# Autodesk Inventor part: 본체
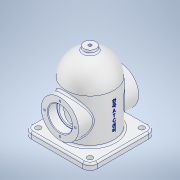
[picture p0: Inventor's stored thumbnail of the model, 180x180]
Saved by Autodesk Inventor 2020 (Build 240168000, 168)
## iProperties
Created: 2021-07
Part Number: 본체
Material: 알루미늄 6061
Document SubType Name: Modeling
Designer: Owner
Density: 2.7 g/cm^3
Appearance: 알루미늄 - 평지
Mass: 865.906 g
Surface Area: 800.746 cm^2
Volume: 320.706 cm^3
Author: Owner
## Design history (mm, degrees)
sketch "스케치1"
  geometry: C1 r 40 at (0, 0); 1 further point
  constraints: 1 centre point, 1 coincident
  dimensions: "d0" = 80 diameter of C1
extrude "돌출1" new body sketch "스케치1" distance "d1" = 124; taper "d2" = 0 deg
fillet "모깎기1" dims "d3" = 40
feature "쉘1" dims "d4" = 8
node "작업 평면1"
sketch "스케치2"
  geometry: C1 r 31 at (0, 48); 1 further point
  constraints: 1 centre point, 1 vertical alignment
  dimensions: "d6" = 62 diameter of C1; "d7" = 48 distance of point (0, 0) C1.centre
extrude "돌출2" join sketch "스케치2" stored distance "d8" = 124; taper "d9" = 0 deg
sketch "스케치3"
  geometry: C1 r 31 at (0, 0) reference; 2 further points
  constraints: 1 coincident
hole "구멍1" sketch "스케치3" at (0, 0) diameter "d10" = 33; stored, may be unused: countersink angle "d14" = 90 deg, drill point angle "d16" = 118 deg; dims "d11" = 6, "d12" = 40, "d13" = 15, "d15" = 49.25
sketch "스케치4"
  geometry: C1 r 16.5 at (0, 0) reference; 2 further points
  constraints: 1 vertical alignment
  dimensions: "d17" = 25.5 distance of C1.centre point (0, 25.5)
hole "구멍2" sketch "스케치4" at (0, 25.5) diameter "d18" = 3.242; stored, may be unused: countersink angle "d22" = 90 deg, drill point angle "d24" = 118 deg; dims "d19" = 8, "d20" = 40, "d21" = 15, "d23" = 10
sketch "스케치5"
  geometry: L1 (-55, 55)-(55, 55); L2 (55, 55)-(55, -55); L3 (55, -55)-(-55, -55); L4 (-55, -55)-(-55, 55); L5 (-55, 55)-(55, -55); L6 (55, 55)-(-55, -55); C1 r 40 at (0, 0) reference; 1 further point
  constraints: 12 end point, 2 midpoint, 2 parallel, 1 horizontal, 1 perpendicular
  dimensions: "d28" = 110 distance of L2.end L3.end; "d29" = 110 distance of L1.end L2.end
extrude "돌출3" join sketch "스케치5" distance "d30" = 10; taper "d31" = 0 deg
fillet "모깎기2" dims "d32" = 12
fillet "모깎기3" dims "d33" = 3
fillet "모깎기4" dims "d34" = 3
node "작업 평면2"
sketch "스케치6"
  geometry: C1 r 10 at (0, 0); 1 further point
  constraints: 1 centre point, 1 coincident
  dimensions: "d36" = 20 diameter of C1
extrude "돌출4" join sketch "스케치6" stored distance "d37" = 10; taper "d38" = 0 deg
sketch "스케치7"
  geometry: C1 r 10 at (0, 0) reference; 2 further points
  constraints: 1 coincident
hole "구멍3" sketch "스케치7" at (0, 0) diameter "d39" = 5.1881; stored, may be unused: countersink angle "d43" = 90 deg, drill point angle "d45" = 118 deg; dims "d40" = 29.25, "d41" = 40, "d42" = 15, "d44" = 36
fillet "모깎기5" dims "d46" = 3
sketch "스케치8"
  geometry: A1 r 9 centre (-43, -43) between (-52, -43) and (-43, -52) reference; 2 further points
  constraints: 1 coincident
hole "구멍4" sketch "스케치8" at (-43, -43) diameter "d47" = 9; stored, may be unused: countersink angle "d51" = 90 deg, drill point angle "d53" = 118 deg; dims "d48" = 29.25, "d49" = 40, "d50" = 15, "d52" = 36
node "작업 평면3"
sketch "스케치9"
  geometry: L1 (0, -43)-(0, 43) reference; 2 further points
  constraints: 1 horizontal alignment, 1 other
  dimensions: "d58" = 48 distance from line of L1 point (48, 0)
feature "엠보싱1" sketch "스케치9" dims "d59" = 0.5, "d60" = 0
chamfer "모따기1" distance "d61" = 1; stored, may be unused: second distance "d62" = 2, angle "d63" = 45 deg
fillet "모깎기6" dims "d64" = 0.3
node "솔리드1"
mirror "미러1"
pattern_circular "원형 패턴1" dims angle "d26" = 360 deg
mirror "미러2"
pattern_circular "원형 패턴2" dims angle "d55" = 360 deg
feature "A9D066F2-1C7D-4E18-AEED-F7BC21143FA4" dims "d10" = 33, "d11" = 6, "d12" = 40, "d13" = 15, "d14" = 90 deg, "d15" = 49.25, "d16" = 118 deg
other parameters: "d35" = -129
